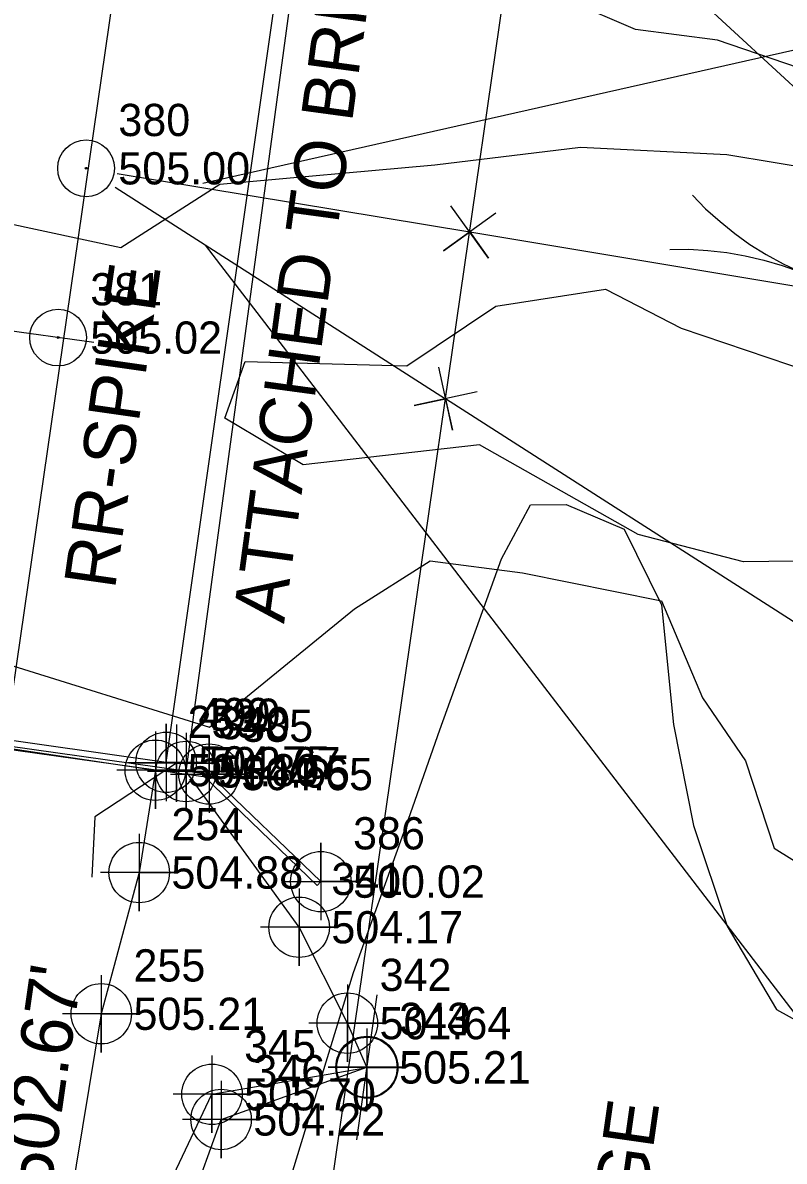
# Model space of a CAD drawing. Extents: x 1698744 to 1699848, y 707609 to 709748.
# Drawn here: x 1699397.1 to 1699456.2, y 708679.7 to 708768 of the extents above; entities that cross this region are included whole.
import ezdxf

# ---------------------------------------------------------------- set-up
doc = ezdxf.new("R2010")
doc.units = 0
for name, color, linetype in [('Exist Horizontal Alignment', 7, 'Continuous'), ('Exist Horizontal T-Line Alignment', 7, 'Continuous'), ('Exist Hydro Jurisdictional Stream or Body of Water', 7, 'Continuous'), ('Exist Hydro Stream Flow Arrow CELL', 7, 'Continuous'), ('Exist Property Corner CELL', 7, 'Continuous'), ('Exist Property Iron Pin Text', 7, 'Continuous'), ('Exist Property Line', 7, 'Continuous'), ('Exist Property Tie Line', 7, 'Continuous'), ('Exist Property Tie Line Leader', 7, 'Continuous'), ('Exist Right of Way Line', 7, 'Continuous'), ('Exist Structure Major Bridge Seat Cogo Elevation', 7, 'Continuous'), ('Exist Structure Major Bridge Seat Cogo Number', 7, 'Continuous'), ('Exist Structure Major Bridge Seat Cogo Point CELL', 7, 'Continuous'), ('Exist Structure Major Bridge Topo Leader', 7, 'Continuous'), ('Exist Structure Major Bridge WW', 7, 'Continuous'), ('Exist Structure Major Bridge WW Cogo Elevation', 7, 'Continuous'), ('Exist Structure Major Bridge WW Cogo Number', 7, 'Continuous'), ('Exist Structure Major Bridge WW Cogo Point CELL', 7, 'Continuous'), ('Exist Structure Major Deck Tunnel Box Culvert', 7, 'Continuous'), ('Exist Structure Major Deck Tunnel Box Culvert Cogo Elevation', 7, 'Continuous'), ('Exist Structure Major Deck Tunnel Box Culvert Cogo Number', 7, 'Continuous'), ('Exist Structure Major Deck Tunnel Box Culvert Cogo Point CELL', 7, 'Continuous'), ('Exist Structure Major Deck Tunnel Box Culvert Text', 7, 'Continuous'), ('Exist Utilities Other Unknown UG SUE', 7, 'Continuous'), ('Exist Utilities Other Unknown UG SUE Text', 7, 'Continuous'), ('Exist Utilities Telephone Pole CELL', 7, 'Continuous'), ('Exist Utilities Telephone UG Cable', 7, 'Continuous'), ('Exist Vegetation Woods Line', 7, 'Continuous'), ('Prop Conc Shoulder Berm Gutter', 7, 'Continuous'), ('Prop Horizontal Alignment Station Label', 7, 'Continuous'), ('Prop North Arrow NAD83 for Plan Sheets CELL', 7, 'Continuous'), ('Prop Roadway Bridge', 7, 'Continuous'), ('Prop Superelevation  Arrow CELL', 7, 'Continuous'), ('Prop Superelevation Label', 7, 'Continuous'), ('Sheet Border Standard 30in CELL', 7, 'Continuous'), ('Sheet Data Field CELL', 7, 'Continuous'), ('Sheet Plot Border Inside CELL', 7, 'Continuous'), ('Sheet Sticker Preliminary CELL', 7, 'Continuous')]:
    doc.layers.add(name, color=color, linetype=linetype)

# ---------------------------------------------------------------- blocks, each defined once
blk = doc.blocks.new('EXIST UTILITIES TELEPHONE POLE')
at = {"layer": 'Exist Utilities Telephone Pole CELL'}
for p, q in [((-0.1135, 0), (0.11325, 0)), ((0, 0), (0, 0))]:
    blk.add_line(p, q, dxfattribs=at)
blk.add_circle((0, 0), 0.04813, dxfattribs=at)
blk = doc.blocks.new('EXIST HYDRO STREAM FLOW ARROW')
at = {"layer": 'Exist Hydro Stream Flow Arrow CELL'}
blk.add_line((0, 0), (0, 0), dxfattribs=at)
for points in [[(-0.1, 0.04575), (-0.07325, 0.03375), (-0.04475, 0.0245), (-0.0165, 0.01575), (0.01175, 0.0095), (0.041, 0.00475), (0.07075, 0.0015), (0.1, 0)], [(-0.1, -0.04575), (-0.07325, -0.03375), (-0.04475, -0.0245), (-0.0165, -0.01575), (0.01175, -0.0095), (0.041, -0.00475), (0.07075, -0.0015), (0.1, 0)]]:
    blk.add_lwpolyline(points, dxfattribs=at)

msp = doc.modelspace()

# ---------------------------------------------------------------- linework, layer by layer
at = {"layer": 'Exist Horizontal Alignment'}
msp.add_line((1699389.789, 708670.951), (1699406.719, 708787.864), dxfattribs=at)
at = {"layer": 'Exist Horizontal T-Line Alignment'}
msp.add_line((1699395.766, 708819.437), (1699550.636, 708676.687), dxfattribs=at)
at = {"layer": 'Exist Hydro Jurisdictional Stream or Body of Water'}
for p, q in [((1699395.686, 708752.496), (1699404.737, 708750.562)), ((1699412.803, 708737.333), (1699414.382, 708741.713)), ((1699389.13, 708720.332), (1699411.615, 708713.364))]:
    msp.add_line(p, q, dxfattribs=at)
for points in [[(1699404.737, 708750.562), (1699412.418, 708755.484), (1699429.099, 708756.972), (1699440.409, 708758.35), (1699451.773, 708757.79), (1699463.027, 708755.911)], [(1699414.382, 708741.713), (1699426.918, 708741.385), (1699433.843, 708746.01), (1699442.355, 708747.336), (1699448.217, 708744.314), (1699458.307, 708740.9), (1699472.77, 708734.355), (1699485.491, 708727.18), (1699475.376, 708723.901), (1699460.943, 708726.272), (1699453.062, 708726.188), (1699444.882, 708728.307), (1699432.562, 708735.26), (1699418.885, 708733.7), (1699412.803, 708737.333)], [(1699411.615, 708713.364), (1699422.853, 708722.529), (1699428.734, 708726.256), (1699435.903, 708725.341), (1699446.694, 708723.162), (1699449.864, 708715.623), (1699453.21, 708710.757), (1699455.427, 708703.963), (1699464.841, 708698.135), (1699487.618, 708694.662), (1699500.743, 708684.083), (1699504.112, 708677.21), (1699519.624, 708664.122), (1699523.948, 708653.239), (1699535.64, 708631.447), (1699541.15, 708623.577), (1699534.343, 708617.805), (1699527.015, 708602.108), (1699520.832, 708584.668), (1699509.419, 708579.385), (1699511.056, 708564.571)]]:
    msp.add_lwpolyline(points, dxfattribs=at)
at = {"layer": 'Exist Property Corner CELL'}
for p, q in [((1699431.805, 708751.77), (1699431.805, 708751.77)), ((1699429.932, 708738.836), (1699429.932, 708738.836))]:
    msp.add_line(p, q, dxfattribs=at)
for points in [[(1699433.838, 708753.225), (1699429.772, 708750.316), (1699431.805, 708751.77), (1699433.26, 708749.737), (1699430.351, 708753.804)], [(1699432.374, 708739.371), (1699427.49, 708738.301), (1699429.932, 708738.836), (1699430.467, 708736.394), (1699429.397, 708741.278)]]:
    msp.add_lwpolyline(points, dxfattribs=at)
at = {"layer": 'Exist Property Line'}
for p, q in [((1699431.805, 708751.77), (1699581.509, 708726.939)), ((1699494.556, 708697.435), (1699429.932, 708738.836))]:
    msp.add_line(p, q, dxfattribs=at)
at = {"layer": 'Exist Property Tie Line'}
for p, q in [((1699404.439, 708756.31), (1699431.805, 708751.77)), ((1699404.297, 708755.258), (1699429.932, 708738.836)), ((1699402.638, 708743.2), (1699370.571, 708747.567))]:
    msp.add_line(p, q, dxfattribs=at)
at = {"layer": 'Exist Property Tie Line Leader'}
for points in [[(1699411.102, 708755.557), (1699478.451, 708770.753), (1699481.948, 708789.926)], [(1699411.281, 708750.735), (1699465.049, 708680.676), (1699461.557, 708660.013)]]:
    msp.add_lwpolyline(points, dxfattribs=at)
at = {"layer": 'Exist Right of Way Line'}
msp.add_line((1699419.48, 708666.652), (1699436.409, 708783.565), dxfattribs=at)
at = {"layer": 'Exist Structure Major Bridge Seat Cogo Point CELL'}
msp.add_lwpolyline([(1699409.053, 708713.572), (1699409.053, 708707.572), (1699409.053, 708710.572), (1699412.053, 708710.572), (1699406.053, 708710.572)], dxfattribs=at)
at = {"layer": 'Exist Structure Major Bridge Topo Leader'}
msp.add_lwpolyline([(1699409.053, 708710.572), (1699402.715, 708706.406), (1699402.488, 708701.715)], dxfattribs=at)
at = {"layer": 'Exist Structure Major Bridge WW'}
msp.add_line((1699419.976, 708701.085), (1699420.253, 708701.373), dxfattribs=at)
for points in [[(1699379.966, 708713.898), (1699411.88, 708709.422)], [(1699380.001, 708714.145), (1699411.573, 708709.718), (1699420.253, 708701.373)], [(1699411.205, 708709.517), (1699419.976, 708701.085)]]:
    msp.add_lwpolyline(points, dxfattribs=at)
at = {"layer": 'Exist Structure Major Bridge WW Cogo Point CELL'}
for points in [[(1699408.573, 708709.718), (1699414.573, 708709.718), (1699411.573, 708709.718), (1699411.573, 708712.718), (1699411.573, 708706.718)], [(1699417.253, 708701.373), (1699423.253, 708701.373), (1699420.253, 708701.373), (1699420.253, 708704.373), (1699420.253, 708698.373)]]:
    msp.add_lwpolyline(points, dxfattribs=at)
for centre in [(1699411.573, 708709.718), (1699420.253, 708701.373)]:
    msp.add_circle(centre, 2.344, dxfattribs=at)
at = {"layer": 'Exist Structure Major Deck Tunnel Box Culvert'}
msp.add_line((1699408.244, 708710.627), (1699420.914, 708799.24), dxfattribs=at)
msp.add_lwpolyline([(1699408.244, 708710.627), (1699383.452, 708714.132), (1699396.13, 708802.924), (1699420.914, 708799.24)], dxfattribs=at)
at = {"layer": 'Exist Structure Major Deck Tunnel Box Culvert Cogo Point CELL'}
msp.add_lwpolyline([(1699405.244, 708710.627), (1699411.244, 708710.627), (1699408.244, 708710.627), (1699408.244, 708713.627), (1699408.244, 708707.627)], dxfattribs=at)
msp.add_circle((1699408.244, 708710.627), 2.344, dxfattribs=at)
at = {"layer": 'Exist Utilities Other Unknown UG SUE'}
msp.add_lwpolyline([(1699423.828, 708686.973), (1699422.31, 708690.395), (1699418.568, 708697.834), (1699409.789, 708709.917), (1699421.783, 708798.336), (1699423.952, 708799.796), (1699433.089, 708799.608), (1699434.593, 708802.424), (1699441.794, 708808.844), (1699441.057, 708818.465), (1699437.884, 708838.376), (1699439.846, 708842.292), (1699441.693, 708843.634)], dxfattribs=at)
at = {"layer": 'Exist Utilities Telephone UG Cable'}
for points in [[(1699289.301, 708261.632), (1699294.428, 708273.117), (1699294.978, 708276.831), (1699297.072, 708285.753), (1699311.338, 708314.926), (1699319.096, 708332.562), (1699334.968, 708376.041), (1699350.587, 708425.328), (1699363.423, 708472.578), (1699375.643, 708525.906), (1699385.352, 708578.539), (1699391.915, 708611.086), (1699402.913, 708666.139), (1699411.801, 708684.877), (1699423.83, 708686.959)], [(1699289.839, 708261.317), (1699295.037, 708272.929), (1699298.75, 708275.67), (1699309.108, 708275.758), (1699298.025, 708276.51), (1699308.57, 708296.279), (1699314.918, 708313.456), (1699314.862, 708313.637), (1699322.03, 708331.106), (1699337.424, 708375.347), (1699353.545, 708424.714), (1699366.132, 708472.255), (1699378.186, 708525.567), (1699388.637, 708577.643), (1699395.958, 708610.123), (1699406.093, 708665.122), (1699412.51, 708682.925), (1699423.828, 708686.973)]]:
    msp.add_lwpolyline(points, dxfattribs=at)
at = {"layer": 'Exist Vegetation Woods Line'}
for points in [[(1699459.438, 708763.772), (1699451.042, 708766.638), (1699444.675, 708767.479), (1699439.461, 708769.711), (1699435.801, 708776.342), (1699436.701, 708783.712), (1699437.768, 708793.908), (1699440.548, 708804.9), (1699444.751, 708816.528), (1699449.896, 708830.762), (1699451.189, 708834.339), (1699452.708, 708842.705), (1699452.773, 708851.633), (1699457.011, 708856.95)], [(1699376.641, 708480.496), (1699399.52, 708581.244), (1699411.026, 708644.91), (1699418.07, 708678.935), (1699422.78, 708694.333), (1699426.698, 708705.173), (1699429.479, 708713.137), (1699431.999, 708720.108), (1699434.28, 708726.418), (1699436.534, 708730.609), (1699439.285, 708730.63), (1699443.789, 708728.726), (1699446.697, 708722.847), (1699447.619, 708713.572), (1699449.181, 708705.721), (1699451.778, 708697.924), (1699455.627, 708691.447), (1699462.744, 708687.53)]]:
    msp.add_lwpolyline(points, dxfattribs=at)
at = {"layer": 'Prop Horizontal Alignment Station Label'}
for centre, radius in [((1699402.034, 708756.709), 2.203), ((1699402.034, 708756.709), 0.0707), ((1699399.857, 708743.578), 2.203), ((1699399.857, 708743.578), 0.0707)]:
    msp.add_circle(centre, radius, dxfattribs=at)
at = {"layer": 'Prop North Arrow NAD83 for Plan Sheets CELL'}
for points in [[(1699409.789, 708712.917), (1699409.789, 708706.917), (1699409.789, 708709.917), (1699412.789, 708709.917), (1699406.789, 708709.917)], [(1699418.568, 708700.834), (1699418.568, 708694.834), (1699418.568, 708697.834), (1699421.568, 708697.834), (1699415.568, 708697.834)], [(1699422.31, 708693.395), (1699422.31, 708687.395), (1699422.31, 708690.395), (1699425.31, 708690.395), (1699419.31, 708690.395)], [(1699423.828, 708689.973), (1699423.828, 708683.973), (1699423.828, 708686.973), (1699426.828, 708686.973), (1699420.828, 708686.973)], [(1699423.83, 708689.959), (1699423.83, 708683.959), (1699423.83, 708686.959), (1699426.83, 708686.959), (1699420.83, 708686.959)], [(1699411.801, 708687.877), (1699411.801, 708681.877), (1699411.801, 708684.877), (1699414.801, 708684.877), (1699408.801, 708684.877)], [(1699412.51, 708685.925), (1699412.51, 708679.925), (1699412.51, 708682.925), (1699415.51, 708682.925), (1699409.51, 708682.925)]]:
    msp.add_lwpolyline(points, dxfattribs=at)
for centre in [(1699409.789, 708709.917), (1699418.568, 708697.834), (1699422.31, 708690.395), (1699423.828, 708686.973), (1699423.83, 708686.959), (1699411.801, 708684.877), (1699412.51, 708682.925)]:
    msp.add_circle(centre, 2.344, dxfattribs=at)
at = {"layer": 'Sheet Border Standard 30in CELL'}
for points in [[(1699407.408, 708713.014), (1699407.408, 708707.014), (1699407.408, 708710.014), (1699410.408, 708710.014), (1699404.408, 708710.014)], [(1699406.153, 708705.077), (1699406.153, 708699.077), (1699406.153, 708702.077), (1699409.153, 708702.077), (1699403.153, 708702.077)], [(1699403.209, 708694.125), (1699403.209, 708688.125), (1699403.209, 708691.125), (1699406.209, 708691.125), (1699400.209, 708691.125)]]:
    msp.add_lwpolyline(points, dxfattribs=at)
for centre in [(1699407.408, 708710.014), (1699406.153, 708702.077), (1699403.209, 708691.125)]:
    msp.add_circle(centre, 2.344, dxfattribs=at)
at = {"layer": 'Sheet Sticker Preliminary CELL'}
msp.add_line((1699383.991, 708713.515), (1699407.408, 708710.014), dxfattribs=at)
msp.add_lwpolyline([(1699407.408, 708710.014), (1699406.153, 708702.077), (1699403.209, 708691.125), (1699399.803, 708670.625), (1699392.316, 708624.595), (1699385.291, 708587.065), (1699376.787, 708545.544), (1699368.797, 708510.472), (1699358.654, 708471.574), (1699347.315, 708431.931), (1699335.282, 708393.417), (1699320.772, 708351.401), (1699309.773, 708322.462), (1699291.819, 708282.074), (1699273.742, 708246.394)], dxfattribs=at)

# ---------------------------------------------------------------- block references
at = {"layer": 'Exist Hydro Stream Flow Arrow CELL', "xscale": 49.99999999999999, "yscale": 50, "rotation": -22.58903539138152}
msp.add_blockref('EXIST HYDRO STREAM FLOW ARROW', (1699452.831, 708750.596), dxfattribs=at)
at = {"layer": 'Exist Utilities Telephone Pole CELL', "xscale": 50, "yscale": 50.00000000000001, "rotation": 82.01205424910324}
msp.add_blockref('EXIST UTILITIES TELEPHONE POLE', (1699423.828, 708686.973), dxfattribs=at)

# ---------------------------------------------------------------- texts
at = {"layer": 'Exist Property Iron Pin Text'}
msp.add_text('RR-SPIKE', height=4, rotation=81.87382, dxfattribs=at).set_placement((1699404.262, 708723.973))
at = {"layer": 'Exist Structure Major Bridge Seat Cogo Elevation'}
msp.add_text('502.67', height=2.5, dxfattribs=at).set_placement((1699411.553, 708709.322))
at = {"layer": 'Exist Structure Major Bridge Seat Cogo Number'}
msp.add_text('399', height=2.5, dxfattribs=at).set_placement((1699411.553, 708713.072))
at = {"layer": 'Exist Structure Major Bridge Topo Leader'}
msp.add_text("SEAT ELEV=502.67'", height=4, rotation=81.87382, dxfattribs=at).set_placement((1699394.72, 708645.428))
at = {"layer": 'Exist Structure Major Bridge WW Cogo Elevation'}
for s, p in [('504.65', (1699414.073, 708708.468)), ('500.02', (1699422.753, 708700.123))]:
    msp.add_text(s, height=2.5, dxfattribs=at).set_placement(p)
at = {"layer": 'Exist Structure Major Bridge WW Cogo Number'}
for s, p in [('385', (1699414.073, 708712.218)), ('386', (1699422.753, 708703.873))]:
    msp.add_text(s, height=2.5, dxfattribs=at).set_placement(p)
at = {"layer": 'Exist Structure Major Deck Tunnel Box Culvert Cogo Elevation'}
msp.add_text('504.75', height=2.5, dxfattribs=at).set_placement((1699410.744, 708709.377))
at = {"layer": 'Exist Structure Major Deck Tunnel Box Culvert Cogo Number'}
msp.add_text('400', height=2.5, dxfattribs=at).set_placement((1699410.744, 708713.127))
at = {"layer": 'Exist Structure Major Deck Tunnel Box Culvert Text'}
msp.add_text('WOOD & STEEL BRIDGE', height=4, rotation=81.87382, dxfattribs=at).set_placement((1699437.666, 708622.034))
at = {"layer": 'Exist Utilities Other Unknown UG SUE Text'}
msp.add_text('ATTACHED TO BRIDGE', height=4, rotation=82.27549, dxfattribs=at).set_placement((1699417.394, 708721.343))
at = {"layer": 'Prop Conc Shoulder Berm Gutter'}
for s, p in [('505.00', (1699404.534, 708755.459)), ('505.02', (1699402.357, 708742.328))]:
    msp.add_text(s, height=2.5, dxfattribs=at).set_placement(p)
at = {"layer": 'Prop Roadway Bridge'}
for s, p in [('504.65', (1699412.289, 708708.667)), ('504.17', (1699421.068, 708696.584)), ('501.64', (1699424.81, 708689.145)), ('505.21', (1699426.328, 708685.723)), ('505.21', (1699426.33, 708685.709)), ('505.70', (1699414.301, 708683.627)), ('504.22', (1699415.01, 708681.675))]:
    msp.add_text(s, height=2.5, dxfattribs=at).set_placement(p)
at = {"layer": 'Prop Superelevation  Arrow CELL'}
for s, p in [('380', (1699404.534, 708759.209)), ('381', (1699402.357, 708746.078))]:
    msp.add_text(s, height=2.5, dxfattribs=at).set_placement(p)
at = {"layer": 'Prop Superelevation Label'}
for s, p in [('340', (1699412.289, 708712.417)), ('341', (1699421.068, 708700.334)), ('342', (1699424.81, 708692.895)), ('343', (1699426.328, 708689.473)), ('344', (1699426.33, 708689.459)), ('345', (1699414.301, 708687.377)), ('346', (1699415.01, 708685.425))]:
    msp.add_text(s, height=2.5, dxfattribs=at).set_placement(p)
at = {"layer": 'Sheet Data Field CELL'}
for s, p in [('253', (1699409.908, 708712.514)), ('254', (1699408.653, 708704.577)), ('255', (1699405.709, 708693.625))]:
    msp.add_text(s, height=2.5, dxfattribs=at).set_placement(p)
at = {"layer": 'Sheet Plot Border Inside CELL'}
for s, p in [('504.80', (1699409.908, 708708.764)), ('504.88', (1699408.653, 708700.827)), ('505.21', (1699405.709, 708689.875))]:
    msp.add_text(s, height=2.5, dxfattribs=at).set_placement(p)

doc.saveas('drawing.dxf')
